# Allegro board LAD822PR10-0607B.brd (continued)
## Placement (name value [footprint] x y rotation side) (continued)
PR32  VALUE}  [R_0402]  194.52 99.25 0 top
PR33  VALUE}  [R_0402]  198.1 103.82 180 top
PR100  VALUE}  [R_0603]  179.22 78.42 180 bottom
PR102  VALUE}  [R_0402]  185.23 83.28 0 top
PR103  VALUE}  [R_0402]  185.23 82.39 0 top
PR106  VALUE}  [R_1206]  181 77.46 90 top
PR107  VALUE}  [R_0402]  186.15 81.5 180 top
PR108  VALUE}  [R_0402]  187.4 81.52 270 bottom
PR109  VALUE}  [R_0402]  186.15 79.73 180 bottom
PR110  VALUE}  [R_0402]  185.23 80.61 0 bottom
PR111  VALUE}  [R_0603]  189.64 78.73 270 bottom
PR112  VALUE}  [R_1206]  192.24 75.81 90 top
PR113  VALUE}  [R_0402]  186.15 80.61 180 top
PR114  VALUE}  [R_0402]  188.5 100.44 90 top
PR115  VALUE}  [R_0402]  197.3 79.62 180 bottom
PR116  VALUE}  [R0402_0OHM]  191.16 100.44 90 top
PR117  VALUE}  [R_0402]  198.59 80.53 270 bottom
PR118  VALUE}  [R_0402]  196.38 80.49 0 bottom
PR120  VALUE}  [R0402_0OHM]  190.27 100.44 90 top
PR121  VALUE}  [R0402_0OHM]  189.39 100.44 90 top
PR122  VALUE}  [R_0402]  186.72 101.35 270 top
PR200  VALUE}  [R_0603]  73.31 103.37 180 top
PR201  VALUE}  [R0402_0OHM]  64.45 104.02 0 top
PR202  VALUE}  [R0402_0OHM]  64.45 106.74 0 top
PR203  VALUE}  [R_1206]  81.09 98.79 180 bottom
PR204  VALUE}  [R_0402]  65.36 107.65 180 top
PR205  VALUE}  [R_0402]  67.78 100.36 0 top
PR206  VALUE}  [R_0603]  65.28 99.31 90 top
PR207  VALUE}  [R_0402]  66.33 107.65 0 top
PR208  VALUE}  [R_0402]  64.44 103.15 0 top
PR209  VALUE}  [R_0402]  64.43 102.17 0 top
PR210  VALUE}  [R_0603]  66.55 100.71 270 top
PR301  VALUE}  [R0402_0OHM]  149.6 26.49 0 bottom
PR302  VALUE}  [R_0402]  150.51 25.57 180 bottom
PR303  VALUE}  [R0402_0OHM]  154.89 32.32 180 bottom
PR304  VALUE}  [R0402_0OHM]  153.17 27.38 270 top
PR305  VALUE}  [R_0402]  153.17 27.38 270 bottom
PR306  VALUE}  [R_0603]  150.94 31.2 90 bottom
PR307  VALUE}  [R_1206]  147.19 31.27 225 top
PR308  VALUE}  [R_0402]  152.28 24.67 270 bottom
PR309  VALUE}  [R_0402]  151.36 25.59 0 bottom
PR310  VALUE}  [R_0402]  151.36 26.49 0 bottom
PR501  VALUE}  [R0402_0OHM]  53.71 12.13 270 bottom
PR502  VALUE}  [R_0402]  51.94 12.13 270 bottom
PR503  VALUE}  [R_0402]  55.56 12.09 180 bottom
PR504  VALUE}  [R_0402]  55.56 10.27 90 bottom
PR505  VALUE}  [R_0402]  56.48 10.27 90 bottom
PR506  VALUE}  [R_1206]  49.05 9.2 270 top
PR601  VALUE}  [R_0402]  165.95 62.62 270 bottom
PR602  VALUE}  [R0402_0OHM]  162.84 62.59 270 top
PR603  VALUE}  [R0402_0OHM]  157.45 61.83 90 bottom
PR604  VALUE}  [R_0402]  165.07 62.62 270 bottom
PR605  VALUE}  [R_0402]  164.18 62.62 270 bottom
PR606  VALUE}  [R0402_0OHM]  165.95 59.48 90 top
PR607  VALUE}  [R0402_0OHM]  165.07 59.48 90 top
PR608  VALUE}  [R_0402]  161.97 62.59 270 top
PR609  VALUE}  [R0402_0OHM]  164.18 59.48 90 top
PR610  VALUE}  [R_0402]  169.21 64.59 90 top
PR611  VALUE}  [R_0402]  161.08 62.59 270 top
PR612  VALUE}  [R_0402]  166.91 61.68 90 top
PR613  VALUE}  [R_0402]  166.46 64.42 0 bottom
PR615  VALUE}  [R_0402]  171.48 72.52 270 top
PR616  VALUE}  [R0402_0OHM]  167.86 61.68 90 top
PR617  VALUE}  [R_0402]  166.88 67.11 0 bottom
PR618  VALUE}  [R_0402]  165.95 61.68 90 top
PR619  VALUE}  [R_0603]  151.03 44.38 180 bottom
PR620  VALUE}  [R0402_0OHM]  170.11 62.79 180 top
PR621  VALUE}  [R_0402]  171 66.39 180 top
PR622  VALUE}  [R_0402]  169.21 67.29 270 top
PR623  VALUE}  [R_0402]  171 65.5 180 top
PR624  VALUE}  [R_0603]  160.87 61.46 90 bottom
PR625  VALUE}  [R_0402]  165.07 61.68 90 top
PR626  VALUE}  [R_0402]  164.18 61.68 90 top
PR627  VALUE}  [R_1206]  148.36 47.94 0 top
PR628  VALUE}  [R_0402]  170.78 66.68 270 bottom
PR629  VALUE}  [R_0402]  166.36 69.18 90 bottom
PR630  VALUE}  [R_0402]  161.6 65.88 270 bottom
PR631  VALUE}  [R_0402]  170.11 63.72 180 top
PR632  VALUE}  [R_0402]  170.98 69.32 270 top
PR633  VALUE}  [R_0402]  170.92 67.92 90 bottom
PR634  VALUE}  [R_0402]  167.48 73.92 270 bottom
PR635  VALUE}  [R_0402]  166.46 71.73 180 bottom
PR636  VALUE}  [R_0402]  159.57 64.8 180 top
PR637  VALUE}  [R_0402]  167.29 68.19 90 bottom
PR638  VALUE}  [R_0402]  170.11 69.31 180 top
PR639  VALUE}  [R_0402]  163.62 69.28 90 bottom
PR640  VALUE}  [R_0402]  160.47 72.51 90 top
PR641  VALUE}  [R_0402]  157.78 65.7 270 top
PR642  VALUE}  [R_0402]  159.49 66.81 180 bottom
PR643  VALUE}  [R_0402]  158.58 64.96 0 bottom
PR644  VALUE}  [R_0402]  159.58 72.51 90 top
PR645  VALUE}  [R_0402]  166.7 72.07 0 top
PR646  VALUE}  [R_0402]  159.5 68.61 180 top
PR647  VALUE}  [R_0402]  166.48 72.66 180 bottom
PR648  VALUE}  [R_0402]  163.86 72.59 270 top
PR649  VALUE}  [R_0402]  159.49 67.67 270 top
PR650  VALUE}  [R_0402]  167.62 72.96 180 top
PR651  VALUE}  [R_0402]  161.57 68.61 0 bottom
PR652  VALUE}  [R_0402]  159.5 69.5 180 top
PR653  VALUE}  [R_0402]  164.67 71.67 90 bottom
PR654  VALUE}  [R_0402]  160.43 63.74 90 bottom
PR655  VALUE}  [R0402_0OHM]  161.71 59.11 180 bottom
PR656  VALUE}  [R_0402]  162.9 71.67 90 bottom
PR657  VALUE}  [R_0402]  163.79 71.67 90 bottom
PR658  VALUE}  [R0402_0OHM]  169.4 95.56 180 bottom
PR659  VALUE}  [R0402_0OHM]  164.44 56.7 180 bottom
PR660  VALUE}  [R_0603]  164.81 55.56 180 bottom
PR661  VALUE}  [R_0603]  158.77 71.32 0 bottom
PR662  VALUE}  [R_0402]  163.53 57.59 0 bottom
PR663  VALUE}  [R_1206]  153 55.87 0 top
PR664  VALUE}  [R_0402]  169.28 93.15 0 bottom
PR665  VALUE}  [R_0603]  169.49 90.8 90 bottom
PR666  VALUE}  [R_0402]  171.43 74.61 180 top
PR667  VALUE}  [R_0603]  169.38 72.45 0 bottom
PR668  VALUE}  [R_0402]  170.29 73.59 180 bottom
PR669  VALUE}  [R_1206]  161.83 92.45 270 top
PR670  VALUE}  [R_0402]  168.38 72.07 180 bottom
PR671  VALUE}  [R0402_0OHM]  170.2 83.75 180 bottom
PR672  VALUE}  [R_0603]  169.49 81.31 90 bottom
PR673  VALUE}  [R_0402]  168.26 69.85 270 bottom
PR674  VALUE}  [R_0603]  170.09 70 0 bottom
PR675  VALUE}  [R_0402]  171.49 71.15 180 bottom
PR676  VALUE}  [R_1206]  161.83 84.32 270 top
PR677  VALUE}  [R_0402]  170.59 71.61 90 top
PR678  VALUE}  [R_0402]  166.91 61.7 90 bottom
PR679  VALUE}  [R0402_0OHM]  147.65 42.6 0 bottom
PR680  VALUE}  [R_0402]  169.28 84.64 0 bottom
PR681  VALUE}  [R_0402]  169.28 94.04 0 bottom
PR703  VALUE}  [R_1206_4P]  182.53 94.7 270 bottom
PR727  VALUE}  [R_0402]  178.64 50.36 0 top
PR729  VALUE}  [R_0402]  175.99 42.78 90 top
PR731  VALUE}  [R_0402]  178.65 43.9 270 top
PR732  VALUE}  [R_0402]  176.86 42.79 0 top
PR737  VALUE}  [R_0402]  182.71 98.74 0 top
PR738  VALUE}  [R_0402]  184.48 98.74 0 top
PR740  VALUE}  [R_0402]  174.15 42.78 90 top
PR741  VALUE}  [R_0402]  179.54 44.76 180 top
PR742  VALUE}  [R_0402]  173.76 53.45 90 top
PR743  VALUE}  [R_1206]  170.27 55.24 90 top
PR745  VALUE}  [R_0402]  171.73 44.27 270 top
PR749  VALUE}  [R_0402]  172.67 52.6 90 top
PR750  VALUE}  [R_0402]  178.18 52.6 90 top
PR751  VALUE}  [R_0402]  170.64 53.65 0 top
PR752  VALUE}  [R_0402]  177.32 53.52 270 top
PR753  VALUE}  [R_0402]  179.56 51.25 180 top
PR754  VALUE}  [R_0402]  179.1 53.52 270 top
PR755  VALUE}  [R_0402]  176.43 53.51 270 top
PR756  VALUE}  [R_0402]  175.53 55.3 0 top
PR757  VALUE}  [R_0402]  171.56 51.87 180 top
PR760  VALUE}  [R_0402]  169.99 49.14 270 top
PR761  VALUE}  [R_0603]  169.73 40.8 270 top
PR762  VALUE}  [R_0402]  192.68 96.51 0 bottom
PR763  VALUE}  [R_0402]  191.56 95.94 180 bottom
PR764  VALUE}  [R_0402]  175.54 53.52 270 top
PR765  VALUE}  [R_1206_4P]  168.33 30.28 180 top
PR769  VALUE}  [R0402_0OHM]  179.56 45.65 180 top
PR770  VALUE}  [R0402_0OHM]  179.56 46.54 180 top
PR771  VALUE}  [R_0603]  170.18 45.51 180 top
PR772  VALUE}  [R_0402]  175.02 42.78 90 top
PR773  VALUE}  [R_0603]  154.22 33.79 0 top
PR774  VALUE}  [R_0402]  179.56 48.57 180 top
PR775  VALUE}  [R0402_0OHM]  179.56 49.46 180 top
PR776  VALUE}  [R_0402]  174.65 53.45 90 top
PR777  VALUE}  [R0402_0OHM]  179.56 47.43 180 top
PR778  VALUE}  [R_0402]  193.59 95.63 180 bottom
PR779  VALUE}  [R0402_0OHM]  170.64 52.76 0 top
PR780  VALUE}  [R_0603]  174.53 62.29 0 top
PR790  VALUE}  [R_0402]  183.53 46.41 0 top
PR791  VALUE}  [R_0402]  184.45 47.37 180 top
PR801  VALUE}  [R_0402]  79.28 10.41 270 top
PR802  VALUE}  [R_0402]  80.19 8.57 180 top
PR803  VALUE}  [R0402_0OHM]  72.16 7.6 90 bottom
PR1201  VALUE}  [R_0402]  108.4 109.52 90 bottom
PR1202  VALUE}  [R_0402]  109.31 110.43 270 bottom
PR1203  VALUE}  [R_0603]  108.99 103.37 270 bottom
PR1204  VALUE}  [R_0402]  106.57 111.31 0 bottom
PR1205  VALUE}  [R_0402]  106.57 109.53 0 bottom
PR1206  VALUE}  [R_0402]  104.66 110.43 270 bottom
PR1207  VALUE}  [R_0402]  105.63 109.52 90 bottom
PR1208  VALUE}  [R_1206]  111.43 110.37 0 bottom
PU100  VALUE}  [SY8286BRAC_QFN20_3X3-S]  180.66 78.59 0 bottom
PU102  VALUE}  [SY8286CRAC_QFN20_3X3-S]  191.71 78.52 0 bottom
PU200  VALUE}  [RT8207PGQW_WQFN20_3X3-S]  69.47 105.22 180 top
PU300  VALUE}  [SY8286RAC_QFN20_3X3-S]  150.6 31.51 315 top
PU500  VALUE}  [SY8033BDBC_DFN10_3X3-S]  50.71 8.07 90 bottom
PU602  VALUE}  [ISL62883CHRTZ-T_TQFN40_5X5-S]  167.11 65.24 90 top
PU603  VALUE}  [AOZ5029QI_QFN24_5X3P5]  162.12 57.2 270 bottom
PU604  VALUE}  [AOZ5029QI_QFN24_5X3P5]  168.06 93.52 270 bottom
PU605  VALUE}  [AOZ5029QI_QFN24_5X3P5]  168.06 84.25 270 bottom
PU606  VALUE}  [ISL95808HRZ-TS2378_DFN8_2X2-S]  152.23 42.9 270 bottom
PU703  VALUE}  [ISL95520HRZ-T_QFN32_4X4-S]  176.59 47.07 180 top
PU800  VALUE}  [RT904225GSP_SO8]  73.91 8.01 90 bottom
PU1200  VALUE}  [NB681GD-Z_QFN13_2X3]  106.13 105.87 0 bottom
Q1901  VALUE}  [2N7002K_SOT23-3]  102.43 22.98 270 top
Q2405  VALUE}  [2N7002K_SOT23-3]  49.56 22.19 0 top
Q2505  VALUE}  [2N7002K_SOT23-3]  210.49 51.87 90 top
Q2601  VALUE}  [2N7002KDWH_SOT363-6]  84.02 14.31 0 top
Q2603  VALUE}  [LMBT3904LT1G_SOT23-3]  102.37 92.21 270 bottom
Q6105  VALUE}  [2N7002K_SOT23-3]  22.76 36.18 90 top
Q6201  VALUE}  [DDTA144VCA-7-F_SOT23-3]  45.43 26.89 0 top
Q6202  VALUE}  [LN2306LT1G_SOT23-3]  114.93 14.41 270 bottom
Q6203  VALUE}  [2N7002K_SOT23-3]  49.56 26.89 0 top
Q6204  VALUE}  [LN2306LT1G_SOT23-3]  52.61 31.97 0 top
Q6205  VALUE}  [LN2306LT1G_SOT23-3]  39.68 17.14 90 top
Q6206  VALUE}  [LN2306LT1G_SOT23-3]  41.43 26.96 0 top
Q6501  VALUE}  [2N7002KDWH_SOT363-6]  93.99 15.9 0 top
Q6502  VALUE}  [2N7002_SOT23-3]  204.37 66.5 180 top
QC2  VALUE}  [DMN66D0LDW-7_SOT363-6]  145.19 16.44 180 bottom
QC5  VALUE}  [DMN66D0LDW-7_SOT363-6]  196.63 14.84 90 bottom
QC6  VALUE}  [DMN66D0LDW-7_SOT363-6]  20.08 43.49 0 top
QL1  VALUE}  [2N7002_SOT23-3]  39.87 80.26 90 top
QX4  VALUE}  [DMN66D0LDW-7_SOT363-6]  18.84 73.34 180 bottom
QX5  VALUE}  [MMBT3904_NL_SOT23-3]  23.94 65.13 90 bottom
QX6  VALUE}  [2N7002K_SOT23-3]  22.93 61.09 90 bottom
QZ11  VALUE}  [LP2301ALT1G_SOT23-3]  38.8 65.59 270 top
R1902  VALUE}  [R_0402]  101.64 21.52 180 top
R2405  VALUE}  [R_0402]  48.99 35.86 90 top
R2407  VALUE}  [R_0402]  24.59 49.31 90 top
R2446  VALUE}  [R_0402]  22.63 49.45 90 top
R2502  VALUE}  [R_0402]  206.66 50.59 90 top
R2504  VALUE}  [R_0402]  206.66 52.43 90 top
R2603  VALUE}  [R_0402]  171.43 112.64 180 top
R2604  VALUE}  [R_0402]  172.42 112.64 0 top
R2606  VALUE}  [R0603_0OHM]  201.64 74.23 180 bottom
R2608  VALUE}  [R_0402]  49.13 33.46 180 top
R2609  VALUE}  [R_0402]  44 32.49 0 top
R2610  VALUE}  [R_0402]  123.35 27.93 180 top
R2611  VALUE}  [R0402_0OHM]  48.21 34.35 0 top
R3022  VALUE}  [R_0402]  33.49 75.29 90 top
R3023  VALUE}  [R_0402]  28.98 76.84 270 top
R3408  VALUE}  [R0402_0OHM]  18.05 49.53 0 bottom
R3409  VALUE}  [R0402_0OHM]  18.05 48.64 0 bottom
R3410  VALUE}  [R0402_0OHM]  18.05 47.62 0 bottom
R3411  VALUE}  [R0402_0OHM]  18.05 46.73 0 bottom
R3416  VALUE}  [R0402_0OHM]  20.83 29.42 0 bottom
R3417  VALUE}  [R0402_0OHM]  20.83 26.69 0 bottom
R3418  VALUE}  [R0402_0OHM]  20.83 27.58 0 bottom
R3419  VALUE}  [R0402_0OHM]  20.83 28.53 0 bottom
R5202  VALUE}  [R_0402]  41.3 104.4 270 top
R5205  VALUE}  [R_0402]  47.07 86.61 180 top
R5206  VALUE}  [R0402_0OHM]  41.18 94.72 90 top
R5207  VALUE}  [R_0402]  49.89 93.86 270 bottom
R5211  VALUE}  [R0805_0OHM]  43.11 105.72 180 top
R5212  VALUE}  [R_0402]  47.48 95.61 270 bottom
R5213  VALUE}  [R0402_0OHM]  35 103.44 0 top
R5214  VALUE}  [R0805_0OHM]  57.08 104.77 180 top
R5215  VALUE}  [R_0402]  50.78 93.86 270 bottom
R5229  VALUE}  [R0603_0OHM]  55.46 97.85 180 top
R5232  VALUE}  [R0603_0OHM]  48.86 100.9 0 top
R5601  VALUE}  [R0805_0OHM]  202.09 15.46 90 bottom
R5605  VALUE}  [R_0402]  214.91 11.54 90 bottom
R5803  VALUE}  [R0402_0OHM]  185.7 60.05 90 top
R5807  VALUE}  [R0402_0OHM]  185.7 53.28 270 top
R5809  VALUE}  [R0805_0OHM]  200.98 50.73 0 bottom
R5810  VALUE}  [R_0402]  202.04 53.14 180 bottom
R5812  VALUE}  [R0402_0OHM]  188.75 52.37 90 top
R6110  VALUE}  [R_0402]  22.66 39.02 180 top
R6201  VALUE}  [R_0402]  44.5 25.13 0 top
R6202  VALUE}  [R_0402]  39.02 27.41 90 top
R6203  VALUE}  [R_0402]  52.19 36.19 0 top
R6206  VALUE}  [R_0402]  120.48 14.6 0 bottom
R6207  VALUE}  [R_0402]  119.49 14.6 180 bottom
R6211  VALUE}  [R_0603]  50.19 20.19 180 top
R6214  VALUE}  [R_0402]  50.96 30.69 180 top
R6505  VALUE}  [R_0402]  50.02 18.98 180 top
R6506  VALUE}  [R_0402]  93.68 12.92 0 top
R6507  VALUE}  [R_0402]  35.92 104.39 180 top
R6508  VALUE}  [R_0402]  93.49 13.81 90 top
R6511  VALUE}  [R0402_0OHM]  28.35 18.55 270 top
R6517  VALUE}  [R_0402]  189.64 52.37 90 top
R6518  VALUE}  [R0402_0OHM]  186.59 53.28 270 top
R6526  VALUE}  [R0402_0OHM]  224.23 12.61 180 top
R6527  VALUE}  [R_0402]  187.86 52.37 90 top
R6528  VALUE}  [R0402_0OHM]  62.03 106.65 90 top
R6529  VALUE}  [R0402_0OHM]  34.94 10.03 0 top
R6530  VALUE}  [R0402_0OHM]  54.38 95.64 270 bottom
R6531  VALUE}  [R_0402]  16.54 43.92 180 top
R6532  VALUE}  [R_0402]  15.89 37.59 0 bottom
R6533  VALUE}  [R_0402]  130.15 36.25 180 top
R6534  VALUE}  [R_0402]  204.04 62.54 0 top
R6535  VALUE}  [R_0402]  205.21 68.38 180 top
RA4  VALUE}  [R_0402]  27.66 29.33 90 bottom
RA10  VALUE}  [R0402_0OHM]  28.18 33.07 270 top
RA12  VALUE}  [R_0402]  21.52 23.68 180 top
RA13  VALUE}  [R_0402]  28.61 31.9 45 bottom
RA14  VALUE}  [R_0402]  35.92 19.24 180 top
RA19  VALUE}  [R_0402]  37.47 31.38 90 top
RA29  VALUE}  [R0402_0OHM]  26.88 32.13 90 bottom
RA30  VALUE}  [R0402_0OHM]  28.79 25.92 270 bottom
RA31  VALUE}  [R0402_0OHM]  18.89 25 90 bottom
RA32  VALUE}  [R0402_0OHM]  25.92 15.44 0 bottom
RA53  VALUE}  [R_0402]  30.64 30.59 90 top
RA55  VALUE}  [R_0402]  26.33 23.34 180 top
RA56  VALUE}  [R_0402]  26.33 22.45 180 top
RA79  VALUE}  [R_0402]  36.57 30.51 0 top
RA80  VALUE}  [R_0402]  23.26 22.41 0 bottom
RA81  VALUE}  [R_0402]  36.45 28.25 0 top
RA82  VALUE}  [R_0402]  23.51 23.35 0 bottom
RA83  VALUE}  [R_0402]  24.24 23.68 180 top
RA84  VALUE}  [R_0402]  25.42 21.46 0 top
RA130  VALUE}  [R_0402]  37.74 25 180 top
RA165  VALUE}  [R_0402]  26.33 22.41 180 bottom
RA166  VALUE}  [R_0402]  26.33 23.35 180 bottom
RA1109  VALUE}  [R_0402]  31.59 30.59 90 top
RA1110  VALUE}  [R0805_0OHM]  37.51 12.03 90 bottom
RA1111  VALUE}  [R0603_0OHM]  24.77 26.51 180 top
RA1114  VALUE}  [R0402_0OHM]  36.48 26.47 90 top
RA1115  VALUE}  [R_0402]  23.84 14.6 270 top
RA1116  VALUE}  [R_0402]  18.66 21.17 180 top
RB1  VALUE}  [R_0402]  223.32 11.72 0 top
RC2  VALUE}  [R_0402]  138.41 62.92 180 bottom
RC3  VALUE}  [R_0402]  132.76 39.87 180 top
RC4  VALUE}  [R_0402]  116.64 30.3 270 bottom
RC5  VALUE}  [R_0402]  103.17 44.38 180 top
RC6  VALUE}  [R_0402]  103.86 46.1 225 top
RC7  VALUE}  [R_0402]  105.37 44.35 180 top
RC9  VALUE}  [R_0402]  109.53 17.78 0 bottom
RC12  VALUE}  [R_0402]  129.37 23.93 0 bottom
RC13  VALUE}  [R_0402]  106.4 39.47 0 bottom
RC14  VALUE}  [R_0402]  129.37 24.89 0 bottom
RC15  VALUE}  [R_0402]  129.89 30.43 270 bottom
RC17  VALUE}  [R_0402]  130.78 30.43 270 bottom
RC18  VALUE}  [R_0402]  108.26 35.15 180 bottom
RC19  VALUE}  [R_0402]  127.05 30.4 270 bottom
RC20  VALUE}  [R_0402]  127.94 30.4 270 bottom
RC21  VALUE}  [R_0402]  103.2 36.62 0 top
RC22  VALUE}  [R_0402]  108.26 34.26 180 bottom
RC23  VALUE}  [R_0402]  126.25 40.89 0 top
RC25  VALUE}  [R_0402]  129 30.41 270 bottom
RC27  VALUE}  [R_0402]  105.13 23.78 270 bottom
RC30  VALUE}  [R_0402]  118.15 22.22 180 bottom
RC43  VALUE}  [R_0402]  138.51 74.86 0 bottom
RC44  VALUE}  [R_0402]  125.32 37.88 0 top
RC45  VALUE}  [R_0402]  134.55 30.58 0 bottom
RC46  VALUE}  [R_0402]  140.62 53.83 90 bottom
RC47  VALUE}  [R_0402]  104.3 29.97 0 top
RC48  VALUE}  [R_0402]  101.44 26.34 90 top
RC50  VALUE}  [R_0402]  104.28 30.86 0 top
RC52  VALUE}  [R_0402]  140.54 58.35 0 bottom
RC53  VALUE}  [R_0402]  118.22 25.21 180 bottom
RC54  VALUE}  [R_0402]  103.55 34.12 0 top
RC56  VALUE}  [R_0402]  98.35 27.16 270 top
RC57  VALUE}  [R_0402]  99.37 27.16 270 top
RC58  VALUE}  [R_0402]  106.48 19.25 90 bottom
RC59  VALUE}  [R_0402]  113.82 30.68 270 bottom
RC60  VALUE}  [R_0402]  116.11 27.74 270 bottom
RC61  VALUE}  [R_0402]  122.38 15.93 0 bottom
RC62  VALUE}  [R_0402]  122.22 30.27 270 bottom
RC63  VALUE}  [R_0402]  121.33 30.27 270 bottom
RC65  VALUE}  [R_0402]  105.18 29.09 270 top
RC68  VALUE}  [R_0402]  96.12 22.67 180 top
RC69  VALUE}  [R_0402]  97.46 26.25 90 top
RC70  VALUE}  [R_0402]  103.2 38.41 0 top
RC72  VALUE}  [R_0402]  104.12 37.52 180 top
RC73  VALUE}  [R_0402]  120.17 35.38 270 top
RC74  VALUE}  [R_0402]  107.7 16.75 90 top
RC75  VALUE}  [R_0402]  96.96 10.43 90 top
RC76  VALUE}  [R0402_0OHM]  101.64 19.36 180 top
RC78  VALUE}  [R_0402]  139.42 71.94 180 bottom
RC79  VALUE}  [R_0402]  142.03 68.13 180 bottom
RC80  VALUE}  [R_0402]  142.03 69.02 180 bottom
RC83  VALUE}  [R_0402]  145.32 70.91 90 top
RC84  VALUE}  [R_0402]  144.25 71.81 180 top
RC88  VALUE}  [R_0402]  105.09 41.63 180 top
RC89  VALUE}  [R_0402]  103.17 43.49 180 top
RC90  VALUE}  [R_0402]  130.65 71.8 90 top
RC91  VALUE}  [R_0402]  129.76 71.8 90 top
RC92  VALUE}  [R_0402]  96.36 31.34 0 top
RC93  VALUE}  [R_0402]  108.56 43.81 180 bottom
RC94  VALUE}  [R_0402]  96.35 30.41 0 top
RC95  VALUE}  [R_0402]  96.35 29.52 0 top
RC96  VALUE}  [R_0402]  122.6 37.71 90 top
RC109  VALUE}  [R_0402]  144.25 76.77 180 top
RC110  VALUE}  [R_0402]  139.42 75.75 180 bottom
RC112  VALUE}  [R_0402]  137.39 77.72 180 bottom
RC113  VALUE}  [R_0402]  139.98 73.73 270 bottom
RC114  VALUE}  [R_0402]  133.06 66.3 270 top
RC115  VALUE}  [R_0402]  130.58 35.31 270 top
RC120  VALUE}  [R_0402]  142.03 74.74 180 bottom
RC123  VALUE}  [R_0402]  105.2 87.8 270 top
RC130  VALUE}  [R_0402]  110.43 16.17 180 top
RC140  VALUE}  [R_0402]  138.92 51.87 180 bottom
RC141  VALUE}  [R_0402]  138 50.99 0 bottom
RC152  VALUE}  [R_0402]  142.03 69.91 180 bottom
RC153  VALUE}  [R_0402]  138.51 69.97 0 bottom
RC157  VALUE}  [R_0402]  142.03 70.8 180 bottom
RC158  VALUE}  [R_0402]  107.65 42.79 0 bottom
RC161  VALUE}  [R_0402]  130.33 73.9 90 top
RC163  VALUE}  [R_0402]  129.76 79.87 90 bottom
RC166  VALUE}  [R_0402]  142.86 42.87 90 top
RC168  VALUE}  [R_0402]  142.86 41.09 90 top
RC170  VALUE}  [R0402_0OHM]  142.84 37.69 270 top
RC171  VALUE}  [R0402_0OHM]  129.77 44.95 180 top
RC172  VALUE}  [R0402_0OHM]  125.25 43.86 90 top
RC173  VALUE}  [R0402_0OHM]  127.04 44.32 180 top
RC175  VALUE}  [R_0402]  140.29 29.27 0 bottom
RC178  VALUE}  [R_0402]  140.29 30.28 0 bottom
RC183  VALUE}  [R_0402]  99.9 32.32 0 top
RC186  VALUE}  [R_0402]  109.85 28.79 180 bottom
RC187  VALUE}  [R_0402]  100.75 31.11 180 top
RC214  VALUE}  [R0402_0OHM]  96.17 20.25 90 top
RC216  VALUE}  [R0402_0OHM]  105.07 42.6 180 top
RC220  VALUE}  [R_0402]  97.64 17.14 180 top
RC223  VALUE}  [R_0402]  100.75 30.22 180 top
RC237  VALUE}  [R_0402]  140.36 26.3 0 bottom
RC239  VALUE}  [R_0402]  130.28 25.84 180 bottom
RC243  VALUE}  [R_0402]  101.3 36.71 90 top
RC248  VALUE}  [R_0402]  140.29 28.25 0 bottom
RC272  VALUE}  [R_0402]  112.18 28.39 180 bottom
RC277  VALUE}  [R_0402]  141.13 32.43 90 bottom
RC288  VALUE}  [R_0402]  108.93 27.83 0 bottom
RC291  VALUE}  [R_0402]  136.7 29.71 90 bottom
RC292  VALUE}  [R_0402]  124.36 29.45 90 bottom
RC293  VALUE}  [R_0402]  141.2 27.24 180 bottom
RC340  VALUE}  [R_0402]  122.41 91.63 180 top
RC341  VALUE}  [R_0402]  121.49 92.51 0 top
RC347  VALUE}  [R_0402]  113.62 28.38 0 bottom
RC348  VALUE}  [R_0402]  138.66 66.27 0 bottom
RC352  VALUE}  [R0603_0OHM]  130.08 32.7 0 top
RC353  VALUE}  [R_0402]  131.54 34.4 90 top
RC354  VALUE}  [R_0402]  114.71 29.38 90 bottom
RC355  VALUE}  [R_0402]  111.27 17.78 0 bottom
RC361  VALUE}  [R_0402]  126.95 32.82 0 top
RC365  VALUE}  [R_0402]  120.98 30.09 0 top
RC366  VALUE}  [R_0402]  121.25 34.48 90 top
RC370  VALUE}  [R_0402]  106.45 16.05 90 bottom
RC371  VALUE}  [R_0402]  105.57 16.96 270 bottom
RC372  VALUE}  [R_0402]  102.95 16.76 0 bottom
RC373  VALUE}  [R_0402]  105.12 18.8 270 bottom
RC374  VALUE}  [R_0402]  125.25 29.45 90 bottom
RC375  VALUE}  [R_0402]  126.14 30.36 270 bottom
RC376  VALUE}  [R_0402]  107.34 16.05 90 bottom
RC377  VALUE}  [R_0402]  108.23 16.96 270 bottom
RC382  VALUE}  [R_0402]  119.14 30.09 0 top
RC384  VALUE}  [R_0402]  132.74 27.69 270 bottom
RC387  VALUE}  [R_0402]  120.46 30.26 270 bottom
RC388  VALUE}  [R_0402]  112.63 10.85 180 top
RC390  VALUE}  [R_0402]  128.27 38.22 180 top
RC391  VALUE}  [R_0402]  103.2 39.3 0 top
RC392  VALUE}  [R0402_0OHM]  111.71 11.81 0 top
RC393  VALUE}  [R_0402]  119.56 30.27 270 bottom
RC394  VALUE}  [R_0402]  140.19 33.33 180 bottom
RC395  VALUE}  [R0402_0OHM]  105.12 38.4 90 top
RC397  VALUE}  [R0402_0OHM]  87.44 15.51 180 top
RC399  VALUE}  [R0402_0OHM]  91.05 15.31 90 top
RC1102  VALUE}  [R_0402]  104.23 40.25 0 top
RC1104  VALUE}  [R_0402]  94.76 23.57 0 top
RC1105  VALUE}  [R_0402]  96.54 24.25 0 top
RC1106  VALUE}  [R_0402]  94.76 24.52 0 top
RC1107  VALUE}  [R_0402]  96.54 25.21 0 top
RC1109  VALUE}  [C_0402]  100.6 29.05 0 top
RC1114  VALUE}  [R0402_0OHM]  137.56 58.35 0 bottom
RC1115  VALUE}  [R0402_0OHM]  137.56 59.24 0 bottom
RC1116  VALUE}  [R0402_0OHM]  137.56 56.19 0 bottom
RC1117  VALUE}  [R0402_0OHM]  137.56 57.08 0 bottom
RC1118  VALUE}  [R_0402]  142.03 71.69 180 bottom
RC1119  VALUE}  [R_0402]  107.46 20.15 270 bottom
RC1120  VALUE}  [R_0402]  117.24 21.27 0 bottom
RC1122  VALUE}  [R_0402]  140.29 31.3 0 bottom
RC1123  VALUE}  [R_0402]  94.76 25.41 0 top
RC1124  VALUE}  [R0402_0OHM]  117.57 15.03 90 bottom
RC1125  VALUE}  [R0402_0OHM]  117.3 24.25 0 bottom
RC1126  VALUE}  [C_0402]  69.37 60.44 90 top
RC1127  VALUE}  [R_0402]  106.68 17.66 270 top
RC1128  VALUE}  [R_0402]  125.25 27.6 90 bottom
RC1129  VALUE}  [R_0402]  124.36 28.52 270 bottom
RC1130  VALUE}  [R_0402]  122.19 28.51 0 bottom
RC1131  VALUE}  [R_0402]  123.1 27.62 180 bottom
RC1134  VALUE}  [R0603_0OHM]  143.54 74.28 270 top
RC1135  VALUE}  [R0402_0OHM]  51.96 47.81 0 top
RC1136  VALUE}  [R0402_0OHM]  106.14 13.96 180 top
RC1137  VALUE}  [R_0402]  103.6 16.44 270 top
RC1138  VALUE}  [R0402_0OHM]  118.94 45.17 180 top
RC1139  VALUE}  [R_0402]  98.68 17.14 0 top
RD1  VALUE}  [R_0402]  68.61 19.29 90 top
RD2  VALUE}  [R_0402]  67.66 19.29 90 top
RD3  VALUE}  [R_0402]  66.56 43.75 0 top
RD4  VALUE}  [R_0402]  53.86 20.82 0 top
RD5  VALUE}  [R0402_0OHM]  53.86 19.81 0 top
RD6  VALUE}  [R_0402]  54.7 45.28 270 top
RD28  VALUE}  [R0402_0OHM]  68.93 21.45 90 top
RD29  VALUE}  [R0402_0OHM]  67.85 21.58 135 top
RD30  VALUE}  [R0402_0OHM]  67.48 42.35 180 top
RD31  VALUE}  [R0402_0OHM]  67.58 59.48 0 top
RD35  VALUE}  [R_0402]  69.37 58.61 90 top
RD38  VALUE}  [R0402_0OHM]  54.78 21.78 180 top
RD39  VALUE}  [R_0402]  54.78 18.86 180 top
RD40  VALUE}  [R0402_0OHM]  54.7 43.44 270 top
RE25  VALUE}  [R_0402]  52.87 45.91 180 top
RE31  VALUE}  [R_0402]  26.53 35.56 0 top
RE32  VALUE}  [R_0402]  85.07 13.22 180 top
RE71  VALUE}  [R_0402]  24.4 49.91 0 bottom
RE72  VALUE}  [R_0402]  24.4 45.14 0 bottom
RE73  VALUE}  [R_0402]  24.4 43.24 0 bottom
RE74  VALUE}  [R_0402]  24.4 42.29 0 bottom
RE75  VALUE}  [R_0402]  24.4 44.19 0 bottom
RE343  VALUE}  [R0402_0OHM]  39.12 31.53 90 top
RE345  VALUE}  [R_0402]  22.63 47.06 270 top
RE347  VALUE}  [R_0402]  24.48 47.06 270 top
RE349  VALUE}  [R0402_0OHM]  27.84 42.16 180 top
RE353  VALUE}  [R_0402]  30.7 59.1 90 top
RE354  VALUE}  [R_0402]  35.03 38.16 180 top
RE355  VALUE}  [R_0402]  33.68 59.1 90 top
RE356  VALUE}  [R_0402]  27.85 45.16 180 top
RE357  VALUE}  [R_0402]  39.41 61.72 180 top
RE358  VALUE}  [R_0402]  27.85 44.2 180 top
RE366  VALUE}  [R_0402]  27.59 41.18 270 top
RE367  VALUE}  [R_0402]  47.27 58.28 90 top
RE368  VALUE}  [R0402_0OHM]  27.59 39.4 270 top
RE380  VALUE}  [R_0402]  37.57 58.1 180 top
RE385  VALUE}  [R_0402]  25.38 45.21 180 top
RE388  VALUE}  [R_0402]  19.13 41.32 0 top
RE389  VALUE}  [R_0402]  45.37 58.28 90 top
RE392  VALUE}  [R_0402]  43.11 33.98 270 top
RE394  VALUE}  [R0402_0OHM]  44.03 33.45 90 top
RE396  VALUE}  [R_0402]  45.18 35.86 90 top
RE397  VALUE}  [R_0402]  44.28 36.78 270 top
RE398  VALUE}  [R0603_0OHM]  24.4 48.19 0 top
RE399  VALUE}  [R_0402]  27.84 50.11 270 top
RE400  VALUE}  [R_0402]  27.85 46.41 180 top
RE404  VALUE}  [R_0402]  34.57 60.02 270 top
RE408  VALUE}  [R_0402]  22.63 42.59 90 top
RE409  VALUE}  [R_0402]  22.63 45.28 270 top
RE410  VALUE}  [R0402_0OHM]  46.13 36.78 270 top
RE413  VALUE}  [R_0402]  50.91 37.93 180 top
RE414  VALUE}  [R_0402]  47.08 35.86 90 top
RE416  VALUE}  [R_0402]  48.03 35.86 90 top
RE420  VALUE}  [R0402_0OHM]  24.4 48.95 0 bottom
RE421  VALUE}  [R0402_0OHM]  24.4 48 0 bottom
RE422  VALUE}  [R0402_0OHM]  24.4 47.05 0 bottom
RE423  VALUE}  [R0402_0OHM]  24.4 46.1 0 bottom
RE424  VALUE}  [R_0402]  35.16 35.52 180 top
RE425  VALUE}  [R_0402]  36.19 35.53 270 top
RE428  VALUE}  [R_0402]  27.45 34.6 180 top
RE432  VALUE}  [R_0402]  86.67 13.89 270 top
RE433  VALUE}  [R0402_0OHM]  24.39 43.06 0 top
RE434  VALUE}  [R0402_0OHM]  31.72 60.02 270 top
RE435  VALUE}  [R_0402]  26.31 53.78 0 top
RE436  VALUE}  [R_0402]  26.31 52.83 0 top
RE437  VALUE}  [R_0402]  27.45 36.51 180 top
RE438  VALUE}  [R0402_0OHM]  49.93 46.86 0 top
RE439  VALUE}  [R_0402]  139.27 32.44 0 bottom
RE440  VALUE}  [R_0402]  49.93 39.87 0 top
RE441  VALUE}  [R_0402]  51.96 44.95 0 top
RE442  VALUE}  [R0402_0OHM]  26.94 48.26 0 top
RE446  VALUE}  [R_0402]  129.56 13.71 0 bottom
RE448  VALUE}  [R0402_0OHM]  26.31 55.68 0 top
RE449  VALUE}  [R0402_0OHM]  25.68 51.89 0 top
RE450  VALUE}  [R_0402]  42.02 22.92 180 top
RE451  VALUE}  [R_0402]  28.88 40.93 180 bottom
RH206  VALUE}  [R_0402]  69.23 44.06 0 top
RH207  VALUE}  [R_0402]  56.52 43.68 0 top
RH209  VALUE}  [R_0402]  70.15 42.16 180 top
RH210  VALUE}  [R_0402]  57.42 42.72 180 top
RH211  VALUE}  [R_0402]  70.15 39.3 180 top
RH212  VALUE}  [R_0402]  57.43 46.41 180 top
RH484  VALUE}  [R_0402]  69.23 41.21 0 top
RH485  VALUE}  [R_0402]  56.52 44.64 0 top
RHO1  VALUE}  [R_0402]  15.66 69.72 180 top
RHO2  VALUE}  [R_0402]  15.66 72.13 180 top
RHO3  VALUE}  [R_0402]  15.66 68.6 180 top
RHO4  VALUE}  [R_0402]  15.66 71.05 180 top
RHO5  VALUE}  [R_0402]  15.66 67.3 180 top
RHO6  VALUE}  [R_0402]  15.66 64.89 180 top
RHO7  VALUE}  [R_0402]  15.66 66.16 180 top
RHO8  VALUE}  [R_0402]  15.66 63.75 180 top
RHO9  VALUE}  [R_0402]  16.53 69.72 0 top
RHO10  VALUE}  [R_0402]  16.53 72.14 0 top
RHO11  VALUE}  [R_0402]  16.53 67.3 0 top
RHO12  VALUE}  [R_0402]  16.53 64.89 0 top
RHR8  VALUE}  [R_0402]  19.96 73.65 0 bottom
RHR11  VALUE}  [R_0402]  19.96 74.54 0 bottom
RL1  VALUE}  [R0402_0OHM]  42.51 85.77 0 top
RL2  VALUE}  [R_0402]  40.76 84.87 0 top
RL4  VALUE}  [R_0402]  42.51 84.87 0 top
RL5  VALUE}  [R_0402]  33.94 90.62 270 top
RL7  VALUE}  [R_0402]  35.07 81.78 0 top
RL8  VALUE}  [R_0603]  37.81 89.97 180 top
RL10  VALUE}  [R_0402]  35.07 80.83 0 top
RL19  VALUE}  [R_0603]  18.9 93.1 180 top
RL20  VALUE}  [R_0603]  18.9 91.17 180 top
RL21  VALUE}  [R_0603]  18.9 85.27 180 top
RL22  VALUE}  [R_0603]  18.9 88.13 180 top
RL23  VALUE}  [R0603_0OHM]  41.35 89.59 180 top
RN19  VALUE}  [R_0402]  144.67 19.43 180 bottom
RN20  VALUE}  [R_0402]  144.42 15.43 0 bottom
RN5201  VALUE}  [RP_0804_8P4R]  44.8 95.63 270 bottom
RN5203  VALUE}  [RP_0804_8P4R]  43.27 94.48 90 bottom
RP58  VALUE}  [RP_0804_8P4R]  19.79 69.87 0 bottom
RP59  VALUE}  [RP_0804_8P4R]  19.77 64.73 0 bottom
RPC1  VALUE}  [RP_0804_8P4R]  144.88 68.02 180 top
RPC3  VALUE}  [RP_0804_8P4R]  139.53 34.74 0 bottom
RPC5  VALUE}  [RP_0804_8P4R]  117.44 18.72 180 bottom
RPE2  VALUE}  [RP_0804_8P4R]  32.49 35.77 270 top
RPE3  VALUE}  [RP_0804_8P4R]  23.21 51.51 180 top
RPE4  VALUE}  [RP_0804_8P4R]  40.43 32.76 90 top
RPE5  VALUE}  [RP_0804_8P4R]  51.15 41.22 180 top
RPE6  VALUE}  [RP_0804_8P4R]  44.21 59.82 270 top
RPE7  VALUE}  [RP_0804_8P4R]  41.23 59.88 270 top
RS1  VALUE}  [R_0402]  199.67 15.76 270 bottom
RS18  VALUE}  [R_0402]  207.55 26.27 90 top
RS19  VALUE}  [R0402_0OHM]  204.37 17.04 90 top
RS20  VALUE}  [R_0402]  205.77 27.19 270 top
RS21  VALUE}  [R_0402]  206.28 17.95 270 top
RS22  VALUE}  [R0402_0OHM]  204.88 27.19 270 top
RS23  VALUE}  [R_0402]  203.1 26.27 90 top
RS24  VALUE}  [R_0402]  207.23 17.95 270 top
RS25  VALUE}  [R0402_0OHM]  209.13 17.04 90 top
RS26  VALUE}  [R0402_0OHM]  201.32 27.19 270 top
RS27  VALUE}  [R0402_0OHM]  208.18 17.04 90 top
RS28  VALUE}  [R_0402]  205.32 17.04 90 top
RS29  VALUE}  [R_0402]  206.66 27.19 270 top
RS30  VALUE}  [R_0402]  203.99 27.19 270 top
RS31  VALUE}  [R_0402]  202.21 26.27 90 top
RS33  VALUE}  [R_0402]  203.42 17.95 270 top
RS34  VALUE}  [R_0402]  209.32 26.27 90 top
RS35  VALUE}  [R_0402]  202.48 17.94 180 top
RS36  VALUE}  [R_0402]  208.44 26.27 90 top
RS37  VALUE}  [R0402_0OHM]  210.14 21.65 0 top
RS38  VALUE}  [R_0402]  210.14 22.54 0 top
RS39  VALUE}  [R_0402]  195.35 16.14 270 bottom
RUS26  VALUE}  [R_0402]  22.69 39.75 0 bottom
RUS27  VALUE}  [R_0402]  22.69 38.79 0 bottom
RUS29  VALUE}  [R0402_0OHM]  15.94 38.65 90 bottom
RX13  VALUE}  [R_0402]  26.8 61.13 270 bottom
RX14  VALUE}  [R_0402]  28.82 64.19 180 bottom
RX15  VALUE}  [R_0402]  27.85 66.09 0 bottom
RX34  VALUE}  [R_0402]  28.78 65.17 180 bottom
RZ18  VALUE}  [R_0402]  53.38 38.44 180 top
RZ19  VALUE}  [R_0402]  53.31 39.35 90 top
RZ20  VALUE}  [R_0402]  94.95 18.79 0 top
RZ21  VALUE}  [R_0402]  93.77 18.71 180 top
RZ62  VALUE}  [R_0402]  45.95 77.02 180 top
RZ64  VALUE}  [R_0402]  48.24 77.02 180 top
RZ65  VALUE}  [R_0402]  45.04 77.97 0 top
RZ66  VALUE}  [R_0402]  45.89 73.21 180 top
RZ115  VALUE}  [R_0402]  48.24 75.12 180 top
RZ116  VALUE}  [R_0402]  34.75 77.02 0 top
RZ117  VALUE}  [R_0402]  35.79 74.23 180 top
RZ119  VALUE}  [R_0402]  36.92 65.2 90 top
RZ120  VALUE}  [R_0402]  47.32 74.16 0 top
RZ121  VALUE}  [R_0402]  48.17 71.31 180 top
RZ122  VALUE}  [R_0402]  45.89 68.89 180 top
RZ123  VALUE}  [R_0402]  48.24 76.07 180 top
RZ124  VALUE}  [R_0402]  45.95 76.07 180 top
RZ125  VALUE}  [R_0402]  48.24 77.97 180 top
RZ126  VALUE}  [R_0402]  45.95 78.93 180 top
RZ127  VALUE}  [R_0402]  45.89 72.26 180 top
RZ1701  VALUE}  [R_0402]  157.19 14.24 0 top
RZ1702  VALUE}  [R_0402]  117.5 12.81 90 top
RZ1703  VALUE}  [R0402_0OHM]  166.17 18.52 0 top
RZ1704  VALUE}  [R0402_0OHM]  165.08 15.74 180 top
RZ1705  VALUE}  [R0603_0OHM]  133.06 15.81 0 bottom
RZ1707  VALUE}  [R_0402]  42.75 78.93 0 top
RZ1708  VALUE}  [R_0402]  45.89 67.88 180 top
RZ1709  VALUE}  [R_0402]  35.79 73.15 180 top
SW1  VALUE}  [SW_SMT1-05-A_4P]  74.56 94.16 90 bottom
T5  VALUE}  [TPC12]  118.46 63.93 0 top
T6  VALUE}  [TPC12]  117.62 64.9 0 top
T9  VALUE}  [TPC12]  138.48 78.07 180 bottom
T10  VALUE}  [TPC12]  136.82 64.36 180 bottom
T11  VALUE}  [TPC12]  140.4 65.41 180 bottom
T12  VALUE}  [TPC12]  111.4 72.94 0 top
T13  VALUE}  [TPC12]  110.95 77.68 180 bottom
T14  VALUE}  [TPC12]  119.92 40.44 0 top
T15  VALUE}  [TPC12]  121.29 40.44 0 top
T16  VALUE}  [TPC12]  111.7 78.91 180 bottom
T17  VALUE}  [TPC12]  112.08 74.23 0 top
T89  VALUE}  [TPC12]  140.99 73.31 180 bottom
T90  VALUE}  [TPC12]  137.05 79.1 180 bottom
T91  VALUE}  [TPC12]  138.41 72.89 180 bottom
T92  VALUE}  [TPC12]  139.5 77.05 180 bottom
T93  VALUE}  [TPC12]  142.41 76.77 0 top
T94  VALUE}  [TPC12]  134.83 77.52 180 bottom
T95  VALUE}  [TPC12]  134.79 78.94 180 bottom
T96  VALUE}  [TPC12]  135.88 79.7 180 bottom
T97  VALUE}  [TPC12]  131.69 69.72 0 top
T98  VALUE}  [TPC12]  133.35 70.04 0 top
T99  VALUE}  [TPC12]  133.21 77.57 180 bottom
T100  VALUE}  [TPC12]  131.52 77.86 180 bottom
T101  VALUE}  [TPC12]  133.49 79.56 180 bottom
T102  VALUE}  [TPC12]  132.46 78.75 180 bottom
T103  VALUE}  [TPC12]  130.75 76.47 180 bottom
T104  VALUE}  [TPC12]  132.01 80.13 180 bottom
T105  VALUE}  [TPC12]  131.09 79.09 180 bottom
T106  VALUE}  [TPC12]  132.24 76.53 180 bottom
T107  VALUE}  [TPC12]  132.07 72.75 0 top
T108  VALUE}  [TPC12]  133.39 72.09 0 top
T110  VALUE}  [TPC12]  135.04 66.96 0 top
T111  VALUE}  [TPC12]  139.04 67.76 0 top
T112  VALUE}  [TPC12]  142.37 67.03 0 top
T113  VALUE}  [TPC12]  113.02 78.91 180 bottom
T114  VALUE}  [TPC12]  112.25 77.54 180 bottom
T115  VALUE}  [TPC12]  115.8 39.38 0 top
T116  VALUE}  [TPC12]  137.63 68.87 0 top
T117  VALUE}  [TPC12]  139.35 67.24 180 bottom
T118  VALUE}  [TPC12]  141.63 69.01 0 top
T119  VALUE}  [TPC12]  132.49 68.64 0 top
T120  VALUE}  [TPC12]  137.89 67.28 180 bottom
T121  VALUE}  [TPC12]  109.69 42.73 180 bottom
T122  VALUE}  [TPC12]  130.47 51.85 0 top
T123  VALUE}  [TPC12]  119.57 51.71 0 top
T124  VALUE}  [TPC12]  109.67 16.71 180 bottom
T125  VALUE}  [TPC12]  132.49 36.13 0 top
T126  VALUE}  [TPC12]  111.85 30.87 180 bottom
T127  VALUE}  [TPC12]  111.65 29.59 180 bottom
T128  VALUE}  [TPC12]  118.08 28.38 180 bottom
T129  VALUE}  [TPC12]  117.62 30.18 180 bottom
T130  VALUE}  [TPC12]  110.34 30.25 180 bottom
T131  VALUE}  [TPC12]  114.51 27.35 180 bottom
T134  VALUE}  [TPC12]  124.1 69.1 0 top
T135  VALUE}  [TPC12]  122.77 69.34 0 top
T136  VALUE}  [TPC12]  118.38 70.37 0 top
T137  VALUE}  [TPC12]  120.49 68.89 0 top
T4931  VALUE}  [TPC12]  39.07 38.35 0 top
T4932  VALUE}  [TPC12]  23.22 48 90 bottom
T4938  VALUE}  [TPC12]  116.5 42.02 0 top
T4941  VALUE}  [TPC12]  138.8 65.34 180 bottom
T4942  VALUE}  [TPC12]  137.53 65.44 180 bottom
T4943  VALUE}  [TPC12]  131.89 58.52 0 top
T4944  VALUE}  [TPC12]  132.68 57.48 0 top
T4945  VALUE}  [TPC12]  111.26 43.57 180 bottom
T4947  VALUE}  [TPC12]  121.56 46.6 0 top
T4948  VALUE}  [TPC12]  119.97 46.03 0 top
T4949  VALUE}  [TPC12]  117.78 66.64 0 top
T4950  VALUE}  [TPC12]  118.25 39.73 0 top
T4951  VALUE}  [TPC12]  118.39 41.14 0 top
T4969  VALUE}  [TPC12]  187.42 50.79 180 bottom
T4973  VALUE}  [TPC12]  216.26 4.17 0 top
T4974  VALUE}  [TPC12]  118.86 38.34 0 top
T4975  VALUE}  [TPC12]  118.27 42.92 0 top
T4976  VALUE}  [TPC12]  40.87 92.51 0 top
T4977  VALUE}  [TPC12]  39.92 93.44 0 top
T4978  VALUE}  [TPC12]  39.58 92.21 0 top
TC3501  VALUE}  [C_1206]  18.63 34.86 0 bottom
TC3502  VALUE}  [C_1206]  20.6 52.62 0 bottom
THM26  VALUE}  [NCT7718W_MSOP8]  174.1 109.32 90 top
TL1  VALUE}  [BOTH_GST5009-E-LF_24P]  29.12 94.2 180 bottom
TPAD1  VALUE}  [ACES_51524-0080N-001_8P]  141.35 12.85 180 bottom
TR3404  VALUE}  [INPAQ_MCM1012B900F06BP_4P]  19.6 48.19 0 top
TR3405  VALUE}  [INPAQ_MCM1012B900F06BP_4P]  22.64 30.09 90 top
TR3406  VALUE}  [INPAQ_MCM1012B900F06BP_4P]  202.2 44.5 180 bottom
TR5201  VALUE}  [INPAQ_MCM1012B900F06BP_4P]  47.71 98.09 270 top
TR5209  VALUE}  [INPAQ_MCM1012B900F06BP_4P]  53.03 93.14 0 bottom
TR5802  VALUE}  [INPAQ_MCM1012B900F06BP_4P]  209.26 15.24 180 top
TR5803  VALUE}  [INPAQ_MCM1012B900F06BP_4P]  202.2 42.66 180 bottom
TR5804  VALUE}  [INPAQ_MCM1012B900F06BP_4P]  202.2 40.82 180 bottom
U3402  VALUE}  [L05ESDL5V0NA-4_SLP2510P8-10-9]  15.59 47.25 270 bottom
U3403  VALUE}  [L05ESDL5V0NA-4_SLP2510P8-10-9]  18.43 27.06 270 bottom
U3504  VALUE}  [AP22802BW5-7_SOT25-5]  16.35 37.47 0 top
U3505  VALUE}  [AP22802BW5-7_SOT25-5]  197.2 22.09 0 bottom
U5201  VALUE}  [RT9724GB_SOT23-5]  39.93 103.45 90 top
U5603  VALUE}  [LNG2DMTR_LGA12_2X2]  219.83 36.3 0 top
UA1  VALUE}  [ALC3234-CG_MQFN48_6X6-S]  34.64 21.47 90 top
UC1  VALUE}  [SKL-U_BGA_1356P-T]  135.31 33.89 270 bottom
UC2  VALUE}  [W25R128FVSIQ_SO8]  126.27 17.77 180 bottom
UC7  VALUE}  [SN74AHC1G08DCKR_SC70-5]  102.63 26.73 0 top
UC12  VALUE}  [74AUP1G07GW_TSSOP5]  104.06 14.1 180 top
UC13  VALUE}  [74AUP1G07GW_TSSOP5]  110.45 14.17 270 top
UC14  VALUE}  [74AUP1G07GW_TSSOP5]  103.92 83.66 0 top
UC15  VALUE}  [SN74AHC1G08DCKR_SC70-5]  114.13 14.11 270 top
UE1  VALUE}  [MEC1404-NU-TR_VTQFP128_14X14]  33.14 39.79 90 top
UE6  VALUE}  [SN74LVC1G06DCKR_SC70-5]  36.08 59.39 0 top
UE7  VALUE}  [YB8251ST23_TSOT-23-3]  79 114.47 0 top
UL1  VALUE}  [RTL8111G-CG_QFN32_4X4-S]  34.37 87.31 270 top
UL3  VALUE}  [SY6288C20AAC_SOT23-5]  32.22 78.48 180 top
US2  VALUE}  [PS8520BTQFN20GTR2_TQFN20_4X4-S]  203.87 23.03 270 top
UUS5  VALUE}  [TPS2543RTER_QFN16_3X3-S]  20.4 38.32 180 bottom
UZ2  VALUE}  [TPS22966DPUR_SON14_2X3-S]  191.03 41.07 0 top
UZ6  VALUE}  [SN74AHC1G08DCKR_SC70-5]  98.28 14.6 180 top
UZ13  VALUE}  [NPCT650JAAWX_TSSOP28]  37.32 77.06 270 top
UZ19  VALUE}  [TPS22961DNYR_WSON8]  159.97 19.58 270 top
UZ21  VALUE}  [TPS22965DSGR_SON8_2X2-S]  160.22 15.98 270 top
WLAN1  VALUE}  [DAN05-67406-0100_67P-T]  198.67 60.43 180 bottom
Y1  VALUE}  [Y_X1A000141000200_2P]  25.81 41 270 top
YC1  VALUE}  [Y_X3G024000DC1H_4P]  142.05 53.19 90 bottom
YC2  VALUE}  [Y_X1A000141000200_2P]  105.31 32.55 180 top
YL1  VALUE}  [Y_X3G025000DC1H_4P]  38.21 94.13 180 top

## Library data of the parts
C229 C2403 C2503 C2602-C2604 C2607-C2609 C2612 C2613 C2715 C3013 C3015 C3017 C3403-C3406 C3504 C3507 C3508 C3510 C5201-C5203 C5206 C5209-C5213 C5225 C5226 C5529-C5531 C5533 C5801-C5804 C6201 C6202 C6204 C6215 C6217 C6219-C6221 C6223 C6225 C6226 CA29-CA31 CA33 CA38-CA40 CA51 CA53-CA56 CA58-CA65 CA69 CA75 CA76 CC59 CC93 CC135 CC136 CC174-CC179 CC181 CC182 CC185 CC186 CC194 CC195 CC199 CC202-CC207 CC211-CC218 CC221 CC223 CC224 CC248-CC253 CC255-CC258 CC265 CC266 CC270-CC273 CC296 CC297 CC1801 CC1802 CC1805 CC1806 CC1808-CC1810 CC1815 CC1816 CC1820-CC1822 CC1824-CC1832 CD19-CD22 CD30-CD32 CD34 CD69 CD74-CD83 CD91 CD92 CE1 CE2 CE8 CE62-CE77 CE79 CE81 CE82 CE84-CE88 CE91 CH100 CH101 CHD1-CHD4 CHO8-CHO11 CHR7-CHR14 CL6 CL11-CL14 CL44-CL46 CN19 CS27 CS30-CS37 CS42 CUS20 CZ23 CZ44 CZ45 CZ50 CZ70 CZ87 CZ92 CZ94 CZ95 CZ1702 CZ1705 EC5205 EC5206 EC5210 EC9701-EC9703 EC9706-EC9712 EC9716 EC9749-EC9753 PC8 PC14 PC16 PC100 PC102 PC103 PC113-PC116 PC127 PC128 PC200-PC203 PC207 PC208 PC210 PC213 PC214 PC502-PC504 PC601 PC602 PC605 PC611 PC613 PC614 PC616-PC621 PC624-PC633 PC635-PC647 PC649-PC655 PC659-PC661 PC663 PC666-PC669 PC671 PC674 PC677 PC679-PC681 PC685-PC688 PC705 PC708 PC711 PC721 PC742 PC744 PC747-PC749 PC751-PC753 PC765 PC768 PC769 PC777 PC779 PC790 PC801 PC803 PC805 PC1201 PC1202 PC1204 PC1205 PC1209 RC1109 RC1126 = C_0402
C2601 C2606 C5204 C5205 C5207 C5224 C5532 C5805 C5806 C6213 C6214 C6218 CA57 CA67 CA68 CA71 CA74 CC220 CC225 CC226 CC279 CC280 CC293-CC295 CD23-CD28 CD35 CD70-CD73 CD84-CD90 CE89 CN20 CZ93 CZ96 CZ97 PC111 PC112 PC119 PC125 PC126 PC204 PC209 PC215-PC220 PC312 PC313 PC501 PC505-PC507 PC603 PC604 PC622 PC662 PC670 PC678 PC750 PC757 PC760 PC762-PC764 PC1001-PC1029 PC1057-PC1061 PC1064-PC1082 PC1129-PC1146 PC1154-PC1156 PC1158 PC1159 PC1161-PC1163 PC1170-PC1184 PC1203 PC1206-PC1208 PC1221-PC1224 = C_0603
C3512 C3513 C6216 CC210 PC104-PC110 PC117 PC118 PC120-PC124 PC205 PC206 PC211 PC212 PC608 PC612 PC656-PC658 PC664 PC665 PC672 PC673 PC761 PC766 PC775 PC776 PC778 PC802 PC804 = C_0805
CA23 = C_0603: room: AUDIO
CA24 CA25 CA32 = C_0402: room: AUDIO
CC9 CC21-CC27 CC57 CC58 = C_0402: room: CPU
CC1803 CC1807 CC1823 CZ98 PC1030-PC1056 PC1083-PC1099 PC1125 PC1126 PC1147-PC1153 PC1164 = C_0201
CD1-CD4 CD12 CD16 CD18 CD29 = C_0402: room: DDR4
CD5-CD10 CD13-CD15 CD17 = C_0603: room: DDR4
CD11 = C_D3: room: DDR4
CD33 = C_D3
CL1-CL4 CL7 CL9 CL16 CL17 = C_0402: room: LAN
CL5 CL8 = C_0603: room: LAN
CL43 TC3501 TC3502 = C_1206
CLRP1 = SHORTPADS: User Part Number: PART#
D2501 = BAS40-04_SOT23-3
D3801 D5203 D5204 = RB551V-30_SOD323-2
D5201 D5202 DA8 = BAT54C-7-F_SOT23-3
DA10 DA13 DA14 = AZ5125-02SPR7G_SOT23-3
DA12 = AZ5123-02SPR7G_SOT23-3
DX4 = BAW56W_SOT323-3
DZ3 DZ4 DZ1701-DZ1704 = RB751S40T1G_SOD523-2
EU3403 EU3404 = AZC199-02SPR7G_SOT23-3
EU3405 U3402 U3403 = L05ESDL5V0NA-4_SLP2510P8-10-9
F5201 F5203 F6202 = F_SMD1812P110TF-24
F6201 = F_NANOSMDC050F-13P2-2
FD1-FD4 = FIDUCIAL_C40M80: room: ETY-ROOM
H1 H3 H4 = H_2P8-G: room: SCREW
H5 H7 = H_2P5-G: room: SCREW
H6 = H_4P0-G: room: SCREW
H8 = H_3P6-G
H9 = H_3P4X2P8N
H10 = H_2P8N
HCPU1 = H_4P2X4P8
HCPU2 HCPU3 = H_3P7
HCPU4 = H_4P3X3P6
HDD1 = ACES_51625-01201-001_12P
HNGFF = H_3P3
JDB1 = ACES_51522-01001-001_10P
JDEG1 = ACES_50521-01041-P01_10P
JDIMM1 = DEREN_40-42271-26001RHF_260P-T: room: DDR4
JDIMM2 = DEREN_40-42261-26001RHF_260P-T: room: DDR4
JEDP = ACES_51540-04001-P01_40P
JFAN1 = ACES_50271-0040N-001_4P
JHDMI = ACON_HMRA4-AK120C_19P
JHP = SINGA_2SJ3095-085111F_6P-T
JIO1 = STARC_111H40-100000-G4-R_40P
JIO2 JSPK = ACES_50278-00401-001_4P
JKB = ACES_50699-03041-P01_30P
JKBBL = ACES_51575-00401-001_4P-T
JLED = ACES_50521-00641-001_6P
JP1 = JUMP_43X79: room: USB
JP13 JP21 PJP102 PJP103 PJP200 PJP302 PJP601 PJP602 PJP701 = JUMP_43X118
JP15 JP17 PJP3 PJP105 PJP106 PJP203 PJP206 PJP501 PJP502 PJP801 PJP802 PJP1201 PJP1202 = JUMP_43X79
JRJ45 = SANTA_130460-3_8P
JSSD1 = BELLW_80159-3221_67P
JUSB1 = TAIWI_USB034-107CRL-TWD_10P-T
JUSB2 = TAITW_PUBAUN-09FLBS1NN4H0_9P-T
JWDB1 = CVILU_CI1804M1VRA-NH_4P
LA1 = MURAT_BLM15PX221SN1D_2P
LA3-LA7 LA10 = MURAT_BLM15BD601SN1D_2P
LA8 LA9 PR116 PR120 PR121 PR201 PR202 PR301 PR303 PR304 PR501 PR602 PR603 PR606 PR607 PR609 PR616 PR620 PR655 PR658 PR659 PR671 PR679 PR769 PR770 PR775 PR777 PR779 PR803 R2611 R3408-R3411 R3416-R3419 R5206 R5213 R5803 R5807 R5812 R6511 R6518 R6526 R6528-R6530 RA31 RA32 RA1114 RC170-RC173 RC214 RC216 RC392 RC395 RC397 RC399 RC1114-RC1117 RC1124 RC1125 RC1135 RC1136 RC1138 RD28-RD31 RD38 RD40 RE343 RE349 RE368 RE394 RE410 RE420-RE423 RE433 RE434 RE438 RE442 RE448 RE449 RS19 RS22 RS25-RS27 RS37 RUS29 RZ1703 RZ1704 = R0402_0OHM
PBATT1 = ACES_50458-01001-P01_10P-T
PC1-PC4 = C_0402: room: DCIN
PC7 = C_0402: room: OTP
PC301 = C_0402: room: ETY-ROOM
PC302 PC304-PC307 PC309 = C_0402: room: 3_5V
PC303 = C_0805: room: 3_5V
PC308 = C_0603: room: 3_5V
PC310 PC311 = C_0603: room: ETY-ROOM
PC606 PC690 = C_25CL33LD
PC1062 PC1063 PC1101 PC1127 PC1128 = C_D2
PD2-PD4 = TVNST52302AB0_SOT523-3
PD5 PD6 = BAV99W_SC70-3
PD102 = SDMK0340L-7-F_SOD323-2
PD704 = LRB715FT1G_SOT323-3
PH601-PH605 PR7 PR13 PR15 PR16 PR18 PR20 PR28 PR29 PR31-PR33 PR102 PR103 PR107-PR110 PR113-PR115 PR117 PR118 PR122 PR204 PR205 PR207-PR209 PR302 PR305 PR308-PR310 PR502-PR505 PR601 PR604 PR605 PR608 PR610-PR613 PR615 PR617 PR618 PR621-PR623 PR625 PR626 PR628-PR654 PR656 PR657 PR662 PR664 PR666 PR668 PR670 PR673 PR675 PR677 PR678 PR680 PR681 PR727 PR729 PR731 PR732 PR737 PR738 PR740-PR742 PR745 PR749-PR757 PR760 PR762-PR764 PR772 PR774 PR776 PR778 PR790 PR791 PR801 PR802 PR1201 PR1202 PR1204-PR1207 R1902 R2405 R2407 R2446 R2502 R2504 R2603 R2604 R2608-R2610 R3022 R3023 R5202 R5205 R5207 R5212 R5215 R5605 R5810 R6110 R6201-R6203 R6206 R6207 R6214 R6505-R6508 R6517 R6527 R6531-R6535 RA4 RA53 RA55 RA56 RA79-RA84 RA130 RA165 RA166 RA1109 RA1115 RA1116 RC2 RC3 RC15 RC62 RC63 RC65 RC83 RC89 RC93 RC94 RC109 RC110 RC112-RC115 RC120 RC123 RC130 RC140 RC141 RC152 RC153 RC157 RC158 RC161 RC163 RC166 RC168 RC175 RC178 RC183 RC186 RC187 RC220 RC223 RC237 RC239 RC243 RC248 RC272 RC277 RC288 RC291-RC293 RC340 RC341 RC347 RC348 RC353-RC355 RC361 RC365 RC366 RC370-RC377 RC382 RC384 RC387 RC388 RC390 RC391 RC393 RC394 RC1102 RC1104-RC1107 RC1118-RC1120 RC1122 RC1123 RC1127-RC1131 RC1137 RC1139 RD35 RD39 RE25 RE31 RE32 RE71-RE75 RE345 RE347 RE353-RE358 RE366 RE367 RE380 RE385 RE388 RE389 RE392 RE396 RE397 RE399 RE400 RE404 RE408 RE409 RE413 RE414 RE416 RE424 RE425 RE428 RE432 RE435-RE437 RE439-RE441 RE446 RE450 RE451 RH206 RH207 RH209-RH212 RH484 RH485 RHO1-RHO12 RHR8 RHR11 RL2 RL7 RL10 RN19 RN20 RS1 RS18 RS20 RS21 RS23 RS24 RS28-RS31 RS33-RS36 RS38 RS39 RUS26 RUS27 RX13-RX15 RX34 RZ18-RZ21 RZ62 RZ64-RZ66 RZ115-RZ117 RZ119-RZ127 RZ1701 RZ1702 RZ1707-RZ1709 = R_0402
PJP301 PJP603 = JUMP_43X39
PJPDC1 = ACES_50458-00601-001_6P-T
PL1 = 5A_Z150_1210_2P: room: DCIN
PL2 = MURAT_BLM15AG102SN1D_2P: room: DCIN
PL4 = 5A_Z150_1210_2P: room: BATT
PL100 PL101 PL200 PL700 = L_7X7X3_M_2P
PL102 PL103 PL606 = 5A_Z150_1210_2P-NPM
PL301 PL501 PL1201 = L_5X5X3_M_2P
PL601 = L_5X5X3_M
PL603-PL605 = L_7X7X4_M
PL704 = L_5X5X3_M_2P-NPM
PQ1 PQ2 PQ709 = 2N7002DW-T-R7_SOT363-6
PQ3 PQ102 = L2N7002WT1G_SC70-3
PQ5 = RHU002N06_SOT323-3
PQ6 = FDV301N_NL_SOT23-3
PQ201 PQ601 = AON7934_DFN3X3A8-10
PQ704 PQ708 PQ740 = SIS412DN-T1-GE3_POWERPAK8-5
PQ710 = LMUN5113T1G_SOT323-3
PQ711 = LTC015EUBFS8TL_UMT3F
PQ717 PQ718 PQ741 = MDU1512RH_POWERDFN56-8-5
PQ720 PQ721 = RUM002N02GT2L_VMT3
PR2 PR3 PR6 PR8 = R_0402: room: BATT
PR4 PR9 = R_0402: room: ETY-ROOM
PR5 = R_1206: room: BATT
PR10-PR12 = R_0402: room: OTP
PR100 PR111 PR200 PR206 PR210 PR306 PR619 PR624 PR660 PR661 PR665 PR667 PR672 PR674 PR761 PR771 PR773 PR780 PR1203 R6211 RL19-RL22 = R_0603
PR106 PR112 PR203 PR307 PR506 PR627 PR663 PR669 PR676 PR743 PR1208 = R_1206
PR703 PR765 = R_1206_4P
PU100 = SY8286BRAC_QFN20_3X3-S
PU102 = SY8286CRAC_QFN20_3X3-S
PU200 = RT8207PGQW_WQFN20_3X3-S
PU300 = SY8286RAC_QFN20_3X3-S
PU500 = SY8033BDBC_DFN10_3X3-S
PU602 = ISL62883CHRTZ-T_TQFN40_5X5-S
PU603-PU605 = AOZ5029QI_QFN24_5X3P5
PU606 = ISL95808HRZ-TS2378_DFN8_2X2-S
PU703 = ISL95520HRZ-T_QFN32_4X4-S
PU800 = RT904225GSP_SO8
PU1200 = NB681GD-Z_QFN13_2X3
Q1901 Q2405 Q2505 Q6105 Q6203 QX6 = 2N7002K_SOT23-3
Q2601 Q6501 = 2N7002KDWH_SOT363-6
Q2603 = LMBT3904LT1G_SOT23-3
Q6201 = DDTA144VCA-7-F_SOT23-3
Q6202 Q6204-Q6206 = LN2306LT1G_SOT23-3
Q6502 QL1 = 2N7002_SOT23-3
QC2 QC5 QC6 QX4 = DMN66D0LDW-7_SOT363-6
QX5 = MMBT3904_NL_SOT23-3
QZ11 = LP2301ALT1G_SOT23-3
R2606 R5229 R5232 RA1111 RC352 RC1134 RE398 RL23 RZ1705 = R0603_0OHM
R5211 R5214 R5601 R5809 RA1110 = R0805_0OHM
RA10 RA29 RA30 = R0402_0OHM: room: AUDIO
RA12-RA14 RA19 = R_0402: room: AUDIO
RB1 = R_0402: room: EC
RC4-RC7 RC9 RC12-RC14 RC17-RC23 RC25 RC27 RC30 RC43-RC48 RC50 RC52-RC54 RC56-RC61 RC68-RC70 RC72-RC75 RC78-RC80 RC90-RC92 RC95 RC96 = R_0402: room: CPU
RC76 = R0402_0OHM: room: CPU
RC84 RC88 = R_0402: room: RTC
RD1-RD4 RD6 = R_0402: room: DDR4
RD5 = R0402_0OHM: room: DDR4
RL1 = R0402_0OHM: room: LAN
RL4 RL5 = R_0402: room: LAN
RL8 = R_0603: room: LAN
RN5201 RN5203 RP58 RP59 RPC1 RPC3 RPC5 RPE2-RPE7 = RP_0804_8P4R
SW1 = SW_SMT1-05-A_4P
T5 T6 T9-T17 = TPC12: room: CPU
T89-T108 T110-T131 T134-T137 T4931 T4932 T4938 T4941-T4945 T4947-T4951 T4969 T4973-T4978 = TPC12
THM26 = NCT7718W_MSOP8
TL1 = BOTH_GST5009-E-LF_24P
TPAD1 = ACES_51524-0080N-001_8P
TR3404-TR3406 TR5201 TR5209 TR5802-TR5804 = INPAQ_MCM1012B900F06BP_4P
U3504 U3505 = AP22802BW5-7_SOT25-5
U5201 = RT9724GB_SOT23-5
U5603 = LNG2DMTR_LGA12_2X2
UA1 = ALC3234-CG_MQFN48_6X6-S: room: AUDIO
UC1 = SKL-U_BGA_1356P-T: room: CPU
UC2 = W25R128FVSIQ_SO8: room: CPU
UC7 UC15 UZ6 = SN74AHC1G08DCKR_SC70-5
UC12-UC14 = 74AUP1G07GW_TSSOP5
UE1 = MEC1404-NU-TR_VTQFP128_14X14
UE6 = SN74LVC1G06DCKR_SC70-5
UE7 = YB8251ST23_TSOT-23-3
UL1 = RTL8111G-CG_QFN32_4X4-S: room: LAN
UL3 = SY6288C20AAC_SOT23-5
US2 = PS8520BTQFN20GTR2_TQFN20_4X4-S
UUS5 = TPS2543RTER_QFN16_3X3-S
UZ2 = TPS22966DPUR_SON14_2X3-S
UZ13 = NPCT650JAAWX_TSSOP28
UZ19 = TPS22961DNYR_WSON8
UZ21 = TPS22965DSGR_SON8_2X2-S
WLAN1 = DAN05-67406-0100_67P-T
Y1 = Y_X1A000141000200_2P
YC1 = Y_X3G024000DC1H_4P: room: CPU
YC2 = Y_X1A000141000200_2P: room: CPU
YL1 = Y_X3G025000DC1H_4P: room: LAN

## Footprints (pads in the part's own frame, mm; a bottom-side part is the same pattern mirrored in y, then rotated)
2N7002_SOT23-3
  oval 1.016x1.524 smd: 1(0,0) 2(0.965,2.083) 3(-0.965,2.083)
2N7002DW-T-R7_SOT363-6
  oval 0.381x1.397 smd: 1(0,0) 2(0.65,0) 3(1.3,0) 4(1.3,1.725) 5(0.65,1.725) 6(0,1.725)
2N7002K_SOT23-3
  oval 1.016x1.524 smd: 1(0,0) 2(0.965,2.083) 3(-0.965,2.083)
2N7002KDWH_SOT363-6
  oval 0.356x0.889 smd: 1(0,0) 2(0.65,0) 3(1.3,0) 4(1.3,1.6) 5(0.65,1.6) 6(0,1.6)
5A_Z150_1210_2P
  rect 0.991x2.997 smd: 1(0,0) 2(2.7,0)
5A_Z150_1210_2P-NPM
  rect 0.991x2.997 smd: 1(0,0) 2(2.7,0)
74AUP1G07GW_TSSOP5
  oval 0.381x1.346 smd: 1(0,0) 2(0.65,0) 3(1.3,0) 4(1.3,1.79) 5(0,1.79)
ACES_50271-0040N-001_4P
  oval 0.787x1.6 smd: 1(0,0) 2(-1.25,0) 3(-2.5,0) 4(-3.75,0)
  rect 2.108x2.997 smd: 5(2.55,-2.9) 6(-6.3,-2.9)
ACES_50278-00401-001_4P
  oval 0.787x1.905 smd: 1(0,0) 2(1.25,0) 3(2.5,0) 4(3.75,0)
  rect 1.295x3.353 smd: 5(-2.85,-4.925) 6(6.6,-4.925)
ACES_50458-00601-001_6P-T
  oval 0.559x1.6 smd: 1(0,0) 2(2,0) 3(4,0) 4(6,0) 5(8,0) 6(10,0)
  rect 1.295x2.057 smd: 7(-3.1,-5.175) 8(13.1,-5.175)
ACES_50458-01001-P01_10P-T
  oval 0.559x1.803 smd: 1(0,0) 2(2,0) 3(4,0) 4(6,0) 5(8,0) 6(10,0) 7(12,0) 8(14,0) 9(16,0) 10(18,0)
  rect 1.295x2.057 smd: 11(-3.1,-5.275) 12(21.1,-5.275)
ACES_50521-00641-001_6P
  oval 0.305x1.143 smd: 1(0,0) 2(0.5,0) 3(1,0) 4(1.5,0) 5(2,0) 6(2.5,0)
  rect 0.406x0.787 smd: 7(-1,-2.675) 8(3.5,-2.675)
ACES_50521-01041-P01_10P
  oval 0.305x0.787 smd: 1(0,0) 2(0.5,0) 3(1,0) 4(1.5,0) 5(2,0) 6(2.5,0) 7(3,0) 8(3.5,0) 9(4,0) 10(4.5,0)
  rect 0.406x0.787 smd: 11(-1,-2.5) 12(5.5,-2.5)
ACES_50699-03041-P01_30P
  oval 0.229x0.787 smd: 1(0,0) 2(0.8,0) 3(1.6,0) 4(2.4,0) 5(3.2,0) 6(4,0) 7(4.8,0) 8(5.6,0) 9(6.4,0) 10(7.2,0) 11(8,0) 12(8.8,0) 13(9.6,0) 14(10.4,0) 15(11.2,0) 16(12,0) 17(12.8,0) 18(13.6,0) 19(14.4,0) 20(15.2,0) 21(16,0) 22(16.8,0) 23(17.6,0) 24(18.4,0) 25(19.2,0) 26(20,0) 27(20.8,0) 28(21.6,0) 29(22.4,0) 30(23.2,0)
  rect 0.559x1.295 smd: 31(-1.475,-3.3) 32(24.675,-3.3)
ACES_51522-01001-001_10P
  oval 0.305x1.295 smd: 1(0,0) 2(0.5,0) 3(1,0) 4(1.5,0) 5(2,0) 6(2.5,0) 7(3,0) 8(3.5,0) 9(4,0) 10(4.5,0)
  rect 2.489x1.905 smd: 11(-2.15,-3.3) 12(6.65,-3.3)
ACES_51524-0080N-001_8P
  oval 0.61x1.295 smd: 1(0,0) 2(1,0) 3(2,0) 4(3,0) 5(4,0) 6(5,0) 7(6,0) 8(7,0)
  rect 2.489x2.21 smd: 9(10,-3.05) 10(-3,-3.05)
ACES_51540-04001-P01_40P
  oval 0.305x1.092 smd: 1(0,0) 2(0.5,0) 3(1,0) 4(1.5,0) 5(2,0) 6(2.5,0) 7(3,0) 8(3.5,0) 9(4,0) 10(4.5,0) 11(5,0) 12(5.5,0) 13(6,0) 14(6.5,0) 15(7,0) 16(7.5,0) 17(8,0) 18(8.5,0) 19(9,0) 20(9.5,0) 21(10,0) 22(10.5,0) 23(11,0) 24(11.5,0) 25(12,0) 26(12.5,0) 27(13,0) 28(13.5,0) 29(14,0) 30(14.5,0) 31(15,0) 32(15.5,0) 33(16,0) 34(16.5,0) 35(17,0) 36(17.5,0) 37(18,0) 38(18.5,0) 39(19,0) 40(19.5,0)
  rect 0.787x2.489 smd: 41(21.2,-3.6) 42(-1.7,-3.6)
